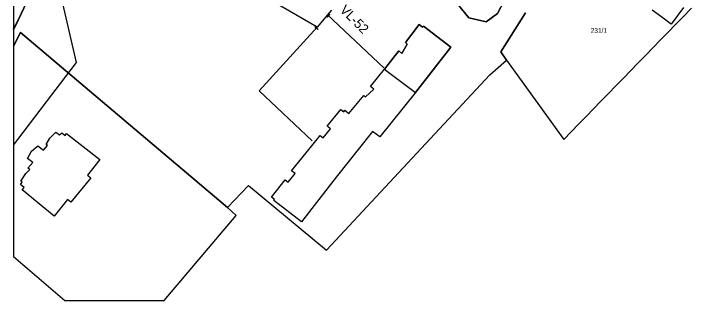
# Model space of a CAD drawing. Extents: x -557590 to -557349, y -1071980 to -1071723.
# Drawn here: x -557590.5 to -557375.2, y -1071980.5 to -1071889.4 of the extents above; entities that cross this region are included whole.
import ezdxf

# ---------------------------------------------------------------- set-up
doc = ezdxf.new("R2010")
doc.units = 0
for name, color, linetype in [('Armatura - popis', 7, 'Continuous'), ('Armatura vodovodní', 7, 'Continuous'), ('Parcela-polygon', 7, 'Continuous'), ('Parcela-text', 7, 'Continuous'), ('Stavební objekt-polygon', 7, 'Continuous'), ('Vodovodní přípojka', 7, 'Continuous'), ('Vodovodní řad', 7, 'Continuous')]:
    doc.layers.add(name, color=color, linetype=linetype)

msp = doc.modelspace()

# ---------------------------------------------------------------- linework, layer by layer
at = {"layer": 'Armatura vodovodní'}
for points in [[(-557490.01, -1071889.65), (-557490.86, -1071890.56), (-557490.92, -1071890.5), (-557490.06, -1071889.59), (-557490.01, -1071889.65)], [(-557494.7, -1071893.52), (-557493.78, -1071894.36), (-557493.83, -1071894.42), (-557494.75, -1071893.58), (-557494.7, -1071893.52)]]:
    msp.add_lwpolyline(points, dxfattribs=at)
at = {"layer": 'Parcela-polygon'}
for p, q in [((-557590.46, -1071878), (-557590.46, -1071894.21)), ((-557590.46, -1071894.21), (-557590.46, -1071894.5)), ((-557590.46, -1071894.5), (-557590.46, -1071899.69)), ((-557590.46, -1071899.69), (-557590.46, -1071966.5)), ((-557590.46, -1071966.5), (-557574.17, -1071980.47)), ((-557574.17, -1071980.47), (-557542.67, -1071980.47))]:
    msp.add_line(p, q, dxfattribs=at)
for points in [[(-557590.46, -1071894.21), (-557589.01, -1071891.45), (-557568.8, -1071848.59), (-557557.24, -1071824.77), (-557548.84, -1071808.44), (-557542.42, -1071797.49), (-557529.5, -1071771.47), (-557511.78, -1071743.08), (-557514.49, -1071741.25), (-557521.38, -1071750.42), (-557524.29, -1071754.35), (-557543.7, -1071784.14), (-557545.78, -1071786.13), (-557549.16, -1071792.19), (-557547.9, -1071792.73), (-557562.91, -1071820.1), (-557590.46, -1071878)], [(-557529.61, -1071787.72), (-557445.83, -1071890.76), (-557440.36, -1071892.03), (-557436.71, -1071889.39), (-557422.96, -1071863.09)], [(-557422.96, -1071863.09), (-557436.71, -1071889.39), (-557440.36, -1071892.03), (-557445.83, -1071890.76), (-557529.61, -1071787.72)], [(-557568.8, -1071848.59), (-557589.01, -1071891.45), (-557590.46, -1071894.5)], [(-557427.91, -1071889.15), (-557435.73, -1071901.54), (-557433.86, -1071904.14), (-557415.71, -1071929.33), (-557413.35, -1071926.9), (-557410.98, -1071924.47), (-557408.61, -1071922.04), (-557406.24, -1071919.61), (-557403.88, -1071917.18), (-557401.52, -1071914.75), (-557399.15, -1071912.32), (-557396.78, -1071909.89), (-557394.41, -1071907.46), (-557392.05, -1071905.03), (-557389.68, -1071902.6), (-557387.32, -1071900.17), (-557384.95, -1071897.74), (-557382.59, -1071895.31), (-557380.22, -1071892.88), (-557377.9, -1071890.5), (-557375.15, -1071887.67)], [(-557377.63, -1071887.44), (-557381.54, -1071892.76), (-557384.6, -1071890.51), (-557387.66, -1071888.26)], [(-557590.46, -1071899.69), (-557588.21, -1071895.34), (-557522.5, -1071950.95), (-557515.88, -1071943.92), (-557491.08, -1071964.55), (-557460.98, -1071932.26), (-557439.15, -1071908.84), (-557433.86, -1071904.14), (-557435.73, -1071901.54), (-557427.91, -1071889.15)], [(-557590.46, -1071894.5), (-557589.01, -1071891.45), (-557590.46, -1071894.21)], [(-557451.53, -1071900.02), (-557462.81, -1071914.41), (-557474.12, -1071928.55), (-557476.47, -1071926.84), (-557487.97, -1071941.29), (-557499.03, -1071955.53), (-557507.75, -1071948.71), (-557507.54, -1071948.45), (-557508.54, -1071947.66), (-557504.2, -1071942.12), (-557503.19, -1071942.92), (-557501.04, -1071940.19), (-557502.18, -1071939.29), (-557497.49, -1071933.61), (-557493.08, -1071928.08), (-557492.11, -1071928.84), (-557489.83, -1071925.94), (-557490.81, -1071925.17), (-557486.52, -1071919.82), (-557485.59, -1071920.55), (-557485.23, -1071920.1), (-557483.97, -1071921.08), (-557479.26, -1071915.39), (-557478.67, -1071915.8), (-557476.08, -1071913.36), (-557477.06, -1071912.58), (-557472.65, -1071906.98), (-557468.12, -1071901.25), (-557467.12, -1071902.04), (-557465.44, -1071899.06), (-557466, -1071898.55), (-557461.59, -1071892.85), (-557460.6, -1071893.74), (-557460.24, -1071893.35), (-557451.53, -1071900.02)], [(-557542.67, -1071980.47), (-557519.71, -1071953.53), (-557522.5, -1071950.95), (-557588.21, -1071895.34), (-557590.46, -1071899.69)], [(-557565.95, -1071941.57), (-557572.24, -1071949.29), (-557573.28, -1071948.45), (-557577.52, -1071953.72), (-557587.72, -1071945.33), (-557587.13, -1071944.58), (-557588.31, -1071943.66), (-557587.69, -1071942.87), (-557588.12, -1071942.6), (-557586.57, -1071940.13), (-557585.33, -1071938.92), (-557585.88, -1071938.48), (-557584.34, -1071936.68), (-557586.01, -1071935.38), (-557584.81, -1071933.04), (-557582.76, -1071931.33), (-557580.95, -1071932.72), (-557579.71, -1071931.27), (-557580.12, -1071930.96), (-557578.92, -1071928.93), (-557577.01, -1071926.99), (-557575.83, -1071927.9), (-557575.18, -1071927.2), (-557574.11, -1071928.08), (-557573.62, -1071927.46), (-557563.03, -1071935.73), (-557567.03, -1071940.7), (-557565.95, -1071941.57)]]:
    msp.add_lwpolyline(points, dxfattribs=at)
msp.add_lwpolyline([(-557472.65, -1071906.98), (-557471.64, -1071907.75), (-557462.81, -1071914.41), (-557451.53, -1071900.02), (-557460.24, -1071893.35), (-557460.6, -1071893.74), (-557461.59, -1071892.85), (-557466, -1071898.55), (-557465.44, -1071899.06), (-557467.12, -1071902.04), (-557468.12, -1071901.25)], close=True, dxfattribs=at)
at = {"layer": 'Stavební objekt-polygon'}
msp.add_lwpolyline([(-557468.12, -1071901.25), (-557472.65, -1071906.98), (-557471.64, -1071907.75), (-557462.81, -1071914.41), (-557451.53, -1071900.02), (-557460.24, -1071893.35), (-557460.6, -1071893.74), (-557461.59, -1071892.85), (-557466, -1071898.55), (-557465.44, -1071899.06), (-557467.12, -1071902.04)], close=True, dxfattribs=at)
at = {"layer": 'Vodovodní přípojka'}
msp.add_line((-557472.9, -1071906.58), (-557490.76, -1071889.8), dxfattribs=at)
msp.add_lwpolyline([(-557495.57, -1071929.77), (-557512.44, -1071913.96), (-557493.98, -1071893.66)], dxfattribs=at)
at = {"layer": 'Vodovodní řad'}
for points in [[(-557489.46, -1071888.25), (-557490.76, -1071889.8), (-557493.98, -1071893.66), (-557519.1, -1071879.11)], [(-557575.53, -1071883.32), (-557570.55, -1071904.9), (-557575.62, -1071911.53), (-557578.43, -1071915.2), (-557589.25, -1071929.32), (-557590.46, -1071931.04)]]:
    msp.add_lwpolyline(points, dxfattribs=at)

# ---------------------------------------------------------------- texts
at = {"layer": 'Armatura - popis'}
msp.add_text('VL-52', height=3, rotation=315, dxfattribs=at).set_placement((-557487.03, -1071888.45))
at = {"layer": 'Parcela-text'}
msp.add_text('231/1', height=1.5, dxfattribs=at).set_placement((-557407.14, -1071895.48))

doc.saveas('drawing.dxf')
